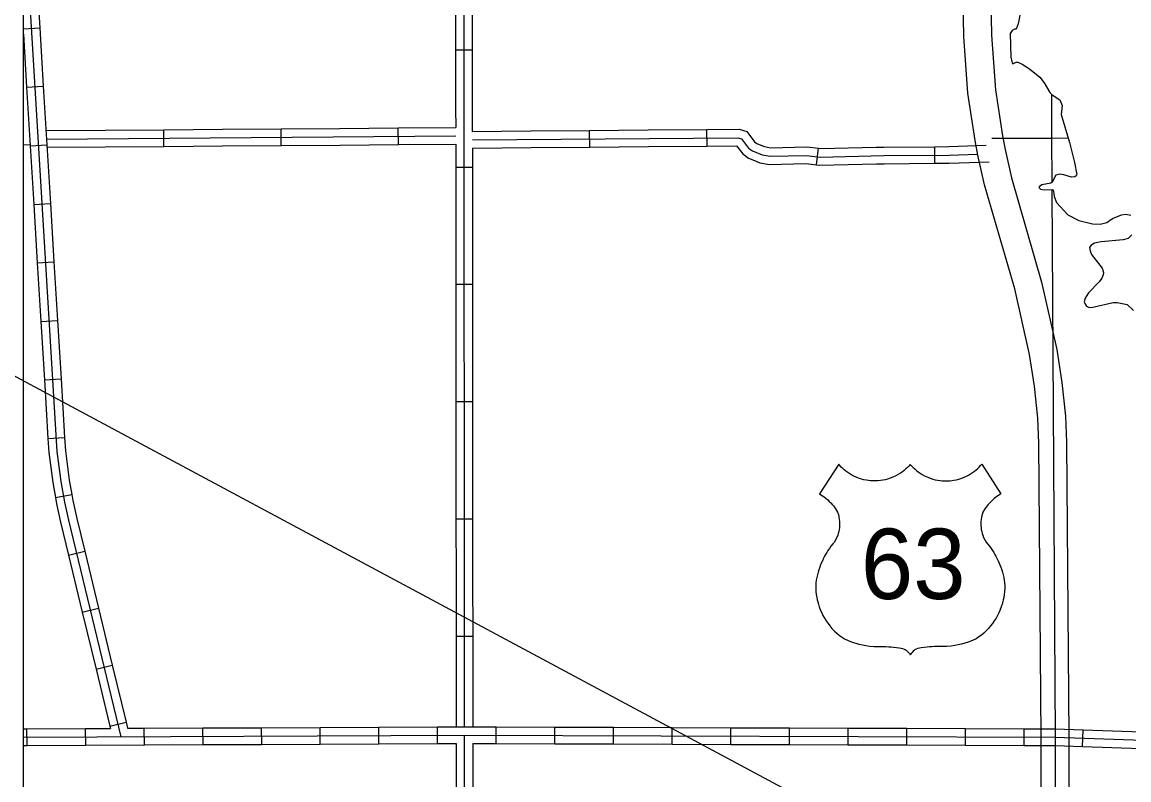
# Model space of a CAD drawing. Extents: x 982240 to 1103002, y 974866 to 1054902.
# Drawn here: x 1018606 to 1028568, y 996650 to 1003474 of the extents above; entities that cross this region are included whole.
import ezdxf

# ---------------------------------------------------------------- set-up
doc = ezdxf.new("R2010")
doc.units = 0
for name, color, linetype in [('15', 7, 'Continuous'), ('22', 7, 'Continuous'), ('32', 7, 'Continuous'), ('45', 7, 'Continuous'), ('5', 7, 'Continuous'), ('9', 7, 'Continuous'), ('R_Draft', 7, 'Continuous')]:
    doc.layers.add(name, color=color, linetype=linetype)

msp = doc.modelspace()

# ---------------------------------------------------------------- linework, layer by layer
at = {"layer": '15'}
for points in [[(1027756.9, 999682.4), (1027748.8, 999907.5), (1027717.7, 1000195.3), (1027673, 1000479.3), (1027540.7, 1001071.6), (1027269.7, 1002010.1), (1027208.3, 1002274.5), (1027183.4, 1002408.2), (1027119.6, 1002835), (1027081.4, 1003344.1), (1027076.2, 1003680.1), (1027091.5, 1003973.3), (1027115.3, 1004225.1), (1027144.1, 1004456.7)], [(1027390.8, 1004416.4), (1027363.8, 1004197.9), (1027340.9, 1003955), (1027326.3, 1003675.5), (1027331.2, 1003355.4), (1027368.2, 1002862.9), (1027430, 1002449.6), (1027453.1, 1002325.7), (1027511.7, 1002073.1), (1027783, 1001133.6), (1027918.7, 1000526.1), (1027965.6, 1000228.2), (1027998.3, 999925.5), (1028006.7, 999691.4)], [(1027778.7, 994300), (1027779, 997032.7), (1027756.8, 999685.8)], [(1028006.8, 999687.9), (1028029, 997033.8), (1028028.7, 994298.4)]]:
    msp.add_lwpolyline(points, dxfattribs=at)
at = {"layer": '22'}
for points in [[(1026600, 999491.1), (1026586.8, 999476.3), (1026574.3, 999463.4), (1026560, 999450), (1026544.5, 999436.8), (1026529.6, 999425.2), (1026511.6, 999412.6), (1026492.2, 999400.5), (1026470.1, 999388.4), (1026442.1, 999375.4), (1026420.6, 999367), (1026396.3, 999359.2), (1026374.1, 999353.4), (1026353.6, 999349.1), (1026332, 999345.8), (1026312.1, 999343.8), (1026284.9, 999342.5), (1026262.8, 999342.8), (1026243.6, 999343.9), (1026225.2, 999345.9), (1026206.7, 999348.7), (1026183.3, 999353.4), (1026161.7, 999359.1), (1026135.4, 999367.6), (1026113.1, 999376.4), (1026092.9, 999385.7), (1026074.3, 999395.4), (1026057.2, 999405.5), (1026038.1, 999418.1), (1026020.5, 999431), (1026005.4, 999443.3), (1025992.6, 999454.6), (1025979.6, 999467.2), (1025966.9, 999480.7), (1025956.5, 999492.5), (1025783.4, 999224.8), (1025795.8, 999217.5), (1025810.5, 999207.8), (1025824.5, 999197.9), (1025843.1, 999183.4), (1025857.9, 999170.6), (1025871.1, 999158.3), (1025884.5, 999144.7), (1025898.2, 999129.5), (1025908.1, 999117.6), (1025917.8, 999105), (1025927.6, 999091.3), (1025937.2, 999076.8), (1025946.1, 999059.8), (1025952.8, 999039), (1025957.9, 999018.2), (1025961.7, 998996.2), (1025963.8, 998975.7), (1025964.5, 998955.8), (1025964, 998937.3), (1025962.8, 998922.4), (1025960.3, 998904.2), (1025956.9, 998887), (1025952.1, 998868.5), (1025946.9, 998852.2), (1025939.8, 998833.9), (1025928.5, 998810.3), (1025917, 998791.8), (1025903.1, 998775.1), (1025886.1, 998753.3), (1025872.4, 998734.2), (1025859.5, 998715.2), (1025847.8, 998696.5), (1025837.9, 998679.7), (1025829.2, 998664), (1025819.4, 998645.3), (1025809, 998623.5), (1025799.6, 998602.1), (1025793.1, 998586.2), (1025785.4, 998565.9), (1025777, 998540.9), (1025770.3, 998520.2), (1025764, 998497.5), (1025758.2, 998471.2), (1025754.3, 998447.9), (1025751.6, 998423.5), (1025750, 998396.9), (1025749.8, 998371.9), (1025751, 998347.4), (1025754, 998318.7), (1025758.4, 998291.5), (1025762.9, 998270.9), (1025767.6, 998252.8), (1025773.5, 998232.4), (1025781.5, 998207), (1025792.9, 998176.1), (1025802.8, 998153.4), (1025814.2, 998130.1), (1025826.7, 998107.2), (1025843, 998080.9), (1025859.9, 998056.8), (1025876.2, 998035.7), (1025894.7, 998014.2), (1025918.6, 997989.4), (1025938.9, 997970.6), (1025959.8, 997953.1)], [(1026600, 999491.1), (1026613.1, 999476.3), (1026625.7, 999463.4), (1026640, 999450), (1026655.4, 999436.8), (1026670.3, 999425.2), (1026688.4, 999412.6), (1026707.8, 999400.5), (1026729.8, 999388.4), (1026757.8, 999375.4), (1026779.3, 999367), (1026803.6, 999359.2), (1026825.8, 999353.4), (1026846.3, 999349.1), (1026867.9, 999345.8), (1026887.8, 999343.8), (1026915, 999342.5), (1026937.1, 999342.8), (1026956.4, 999343.9), (1026974.7, 999345.9), (1026993.3, 999348.7), (1027016.6, 999353.4), (1027038.2, 999359.1), (1027064.5, 999367.6), (1027086.8, 999376.4), (1027107, 999385.7), (1027125.6, 999395.4), (1027142.7, 999405.5), (1027161.9, 999418.1), (1027179.4, 999431), (1027194.5, 999443.3), (1027207.3, 999454.6), (1027220.3, 999467.2), (1027233.1, 999480.7), (1027243.4, 999492.5), (1027416.5, 999224.8), (1027404.2, 999217.5), (1027389.4, 999207.8), (1027375.5, 999197.9), (1027356.9, 999183.4), (1027342, 999170.6), (1027328.9, 999158.3), (1027315.5, 999144.7), (1027301.7, 999129.5), (1027291.9, 999117.6), (1027282.2, 999105), (1027272.3, 999091.3), (1027262.7, 999076.8), (1027253.9, 999059.8), (1027247.2, 999039), (1027242, 999018.2), (1027238.2, 998996.2), (1027236.2, 998975.7), (1027235.5, 998955.8), (1027236, 998937.3), (1027237.2, 998922.4), (1027239.6, 998904.2), (1027243, 998887), (1027247.8, 998868.5), (1027253, 998852.2), (1027260.2, 998833.9), (1027271.4, 998810.3), (1027283, 998791.8), (1027296.9, 998775.1), (1027313.8, 998753.3), (1027327.6, 998734.2), (1027340.4, 998715.2), (1027352.2, 998696.5), (1027362.1, 998679.7), (1027370.8, 998664), (1027380.5, 998645.3), (1027391, 998623.5), (1027400.4, 998602.1), (1027406.9, 998586.2), (1027414.5, 998565.9), (1027423, 998540.9), (1027429.6, 998520.2), (1027435.9, 998497.5), (1027441.7, 998471.2), (1027445.6, 998447.9), (1027448.4, 998423.5), (1027450, 998396.9), (1027450.1, 998371.9), (1027449, 998347.4), (1027446, 998318.7), (1027441.5, 998291.5), (1027437.1, 998270.9), (1027432.3, 998252.8), (1027426.4, 998232.4), (1027418.5, 998207), (1027407, 998176.1), (1027397.2, 998153.4), (1027385.8, 998130.1), (1027373.2, 998107.2), (1027356.9, 998080.9), (1027340.1, 998056.8), (1027323.8, 998035.7), (1027305.3, 998014.2), (1027281.3, 997989.4), (1027261, 997970.6), (1027240.1, 997953.1)], [(1025959.8, 997953.1), (1025981.5, 997936.6), (1026007.6, 997919.6), (1026040.4, 997904.9), (1026078.7, 997890.2), (1026110, 997880.1), (1026138.1, 997872.3), (1026169.9, 997864.9), (1026199.8, 997859.4), (1026231.9, 997855), (1026272.4, 997851.5), (1026303.4, 997850.4), (1026329.9, 997850.6), (1026355.6, 997850.3), (1026381.4, 997849.5), (1026405.9, 997848.3), (1026427.2, 997846.8), (1026448.2, 997845.1), (1026475.1, 997842.3), (1026501.4, 997839), (1026517.1, 997836.8), (1026530.2, 997834.3), (1026545.9, 997827.7), (1026554.9, 997822.7), (1026562.8, 997817.5), (1026573.6, 997808.8), (1026583.9, 997798.4), (1026592.3, 997787.6), (1026600, 997775.1)], [(1027240.1, 997953.1), (1027218.4, 997936.6), (1027192.3, 997919.6), (1027159.6, 997904.9), (1027121.3, 997890.2), (1027090, 997880.1), (1027061.8, 997872.3), (1027030, 997864.9), (1027000.1, 997859.4), (1026968, 997855), (1026927.5, 997851.5), (1026896.6, 997850.4), (1026870.1, 997850.6), (1026844.3, 997850.3), (1026818.5, 997849.5), (1026794.1, 997848.3), (1026772.8, 997846.8), (1026751.8, 997845.1), (1026724.9, 997842.3), (1026698.6, 997839), (1026682.8, 997836.8), (1026669.8, 997834.3), (1026654, 997827.7), (1026645, 997822.7), (1026637.1, 997817.5), (1026626.3, 997808.8), (1026616, 997798.4), (1026607.6, 997787.6), (1026600, 997775.1)]]:
    msp.add_lwpolyline(points, dxfattribs=at)
at = {"layer": '32'}
for p, q in [((1018616.9, 1003414.1), (1018763.6, 1003423)), ((1018646, 1002886.9), (1018795.7, 1002896)), ((1018678, 1002359.9), (1018827.7, 1002369)), ((1018710.1, 1001832.8), (1018859.8, 1001841.9)), ((1018742.1, 1001305.8), (1018891.9, 1001314.9)), ((1018774.2, 1000778.8), (1018923.9, 1000787.9)), ((1018806.3, 1000251.8), (1018956, 1000260.9)), ((1018838.3, 999724.7), (1018988, 999733.9)), ((1018904.7, 999193.2), (1019052.6, 999218.7)), ((1019023, 998673.7), (1019168.8, 998708.9)), ((1019147.1, 998160.5), (1019292.9, 998195.7)), ((1019271.2, 997647.3), (1019417, 997682.5)), ((1019395.3, 997134.1), (1019541.1, 997169.3)), ((1019395.3, 997134.1), (1019400.3, 997113.6)), ((1019541.1, 997169.3), (1019554.4, 997114.3)), ((1018649.8, 996960.3), (1018649.2, 997110.3)), ((1019177.2, 997112.6), (1019400.3, 997113.6)), ((1019177.8, 996962.6), (1019177.2, 997112.6)), ((1019554.4, 997114.3), (1019705.2, 997115)), ((1019705.8, 996965), (1019705.2, 997115)), ((1020233.8, 996967.3), (1020233.2, 997117.3)), ((1020761.8, 996969.6), (1020761.2, 997119.6)), ((1021289.8, 996972), (1021289.2, 997122)), ((1021817.8, 996974.3), (1021817.1, 997124.3)), ((1022345.8, 996976.6), (1022345.1, 997126.6)), ((1022873.2, 996976.7), (1022873.7, 997126.7)), ((1023401.2, 996974.9), (1023401.7, 997124.9)), ((1023929.2, 996973.1), (1023929.7, 997123.1)), ((1024457.2, 996971.3), (1024457.7, 997121.3)), ((1024985.2, 996969.5), (1024985.7, 997119.5)), ((1025513.2, 996967.8), (1025513.7, 997117.8)), ((1026041.2, 996966), (1026041.7, 997116)), ((1026569.2, 996964.2), (1026569.7, 997114.2)), ((1027097.2, 996962.4), (1027097.7, 997112.4)), ((1027625.2, 996960.6), (1027625.7, 997110.6)), ((1028150.8, 996951.1), (1028155.9, 997101.1)), ((1022345.8, 996976.6), (1022512.2, 996977.4)), ((1022512.2, 996977.4), (1022512.3, 996523.3)), ((1022662.2, 996977.4), (1022873.2, 996976.7)), ((1022662.2, 996977.4), (1022662.3, 996523.3))]:
    msp.add_line(p, q, dxfattribs=at)
for points in [[(1018616.9, 1004576.7), (1018919.3, 999605.7), (1018954.6, 999337.6), (1018986.9, 999149.7), (1019022.7, 998987.9), (1019494.5, 997037.2)], [(1018731.6, 1003950), (1018763.6, 1003423)], [(1018763.6, 1003423), (1018795.7, 1002896)], [(1018616.9, 1003364.4), (1018646, 1002886.9)], [(1018646, 1002886.9), (1018678, 1002359.9)], [(1018795.7, 1002896), (1018827.7, 1002369)], [(1018678, 1002359.9), (1018710.1, 1001832.8)], [(1018827.7, 1002369), (1018859.8, 1001841.9)], [(1018710.1, 1001832.8), (1018742.1, 1001305.8)], [(1018859.8, 1001841.9), (1018891.9, 1001314.9)], [(1018891.9, 1001314.9), (1018923.9, 1000787.9)], [(1018742.1, 1001305.8), (1018774.2, 1000778.8)], [(1018774.2, 1000778.8), (1018806.3, 1000251.8)], [(1018923.9, 1000787.9), (1018956, 1000260.9)], [(1018806.3, 1000251.8), (1018838.3, 999724.7)], [(1018956, 1000260.9), (1018988, 999733.9)], [(1018838.3, 999724.7), (1018846, 999598.6), (1018881.8, 999326.5), (1018904.7, 999193.2)], [(1018988, 999733.9), (1018995.4, 999613), (1019030.1, 999349), (1019052.6, 999218.7)], [(1018904.7, 999193.2), (1018914.7, 999135.5), (1018951, 998971.3), (1019023, 998673.7)], [(1019052.6, 999218.7), (1019061.9, 999164.4), (1019097.1, 999005.2), (1019168.8, 998708.9)], [(1019023, 998673.7), (1019147.1, 998160.5)], [(1019168.8, 998708.9), (1019292.9, 998195.7)], [(1019147.1, 998160.5), (1019271.2, 997647.3)], [(1019292.9, 998195.7), (1019417, 997682.5)], [(1019271.2, 997647.3), (1019395.3, 997134.1)], [(1019417, 997682.5), (1019541.1, 997169.3)], [(1018616.9, 997110.2), (1018649.2, 997110.3)], [(1018616.9, 997033.8), (1022585.8, 997051.3), (1027904, 997033.2)], [(1018649.2, 997110.3), (1019177.2, 997112.6)], [(1019705.2, 997115), (1020233.2, 997117.3)], [(1020233.2, 997117.3), (1020761.2, 997119.6)], [(1020761.2, 997119.6), (1021289.2, 997122)], [(1021289.2, 997122), (1021817.1, 997124.3)], [(1021817.1, 997124.3), (1022345.1, 997126.6)], [(1022345.1, 997126.6), (1022585.8, 997127.7), (1022873.7, 997126.7)], [(1022585.8, 997051.3), (1022587.5, 991642.2), (1022477.3, 987555.6)], [(1022873.7, 997126.7), (1023401.7, 997124.9)], [(1023401.7, 997124.9), (1023929.7, 997123.1)], [(1023929.7, 997123.1), (1024457.7, 997121.3)], [(1024457.7, 997121.3), (1024985.7, 997119.5)], [(1024985.7, 997119.5), (1025513.7, 997117.8)], [(1025513.7, 997117.8), (1026041.7, 997116)], [(1026041.7, 997116), (1026569.7, 997114.2)], [(1026569.7, 997114.2), (1027097.7, 997112.4)], [(1027097.7, 997112.4), (1027625.7, 997110.6)], [(1027625.7, 997110.6), (1027905.4, 997109.6), (1028155.9, 997101.1)], [(1027904, 997033.2), (1033266.6, 996849.8)], [(1028155.9, 997101.1), (1028683.6, 997083)], [(1018616.9, 996960.2), (1018649.8, 996960.3)], [(1018649.8, 996960.3), (1019177.8, 996962.6)], [(1019177.8, 996962.6), (1019705.8, 996965)], [(1019705.8, 996965), (1020233.8, 996967.3)], [(1020233.8, 996967.3), (1020761.8, 996969.6)], [(1020761.8, 996969.6), (1021289.8, 996972)], [(1021289.8, 996972), (1021817.8, 996974.3)], [(1021817.8, 996974.3), (1022345.8, 996976.6)], [(1022873.2, 996976.7), (1023401.2, 996974.9)], [(1023401.2, 996974.9), (1023929.2, 996973.1)], [(1023929.2, 996973.1), (1024457.2, 996971.3)], [(1024457.2, 996971.3), (1024985.2, 996969.5)], [(1024985.2, 996969.5), (1025513.2, 996967.8)], [(1025513.2, 996967.8), (1026041.2, 996966)], [(1026041.2, 996966), (1026569.2, 996964.2)], [(1026569.2, 996964.2), (1027097.2, 996962.4)], [(1027097.2, 996962.4), (1027625.2, 996960.6)], [(1027625.2, 996960.6), (1027902.6, 996959.6), (1028150.8, 996951.1)], [(1028150.8, 996951.1), (1028678.5, 996933.1)]]:
    msp.add_lwpolyline(points, dxfattribs=at)
at = {"layer": '45'}
for p, q in [((1022580.4, 1004281.2), (1022585.7, 997127.7)), ((1022507.6, 1003225.1), (1022657.6, 1003225.2)), ((1022508, 1002697.1), (1022508.1, 1002525.1)), ((1022658, 1002697.2), (1022658.1, 1002489.8)), ((1020937.1, 1002363.1), (1020936, 1002513.1)), ((1021991.9, 1002521.1), (1022508.1, 1002525.1)), ((1021993.1, 1002371.1), (1021991.9, 1002521.1)), ((1018820, 1002496.9), (1019352, 1002501)), ((1018824.6, 1002420.5), (1022508.2, 1002448.7)), ((1019881.1, 1002355), (1019880, 1002505)), ((1022658.1, 1002489.8), (1023185.5, 1002494.2)), ((1023714.8, 1002348.6), (1023713.5, 1002498.6)), ((1024770.7, 1002357.4), (1024769.5, 1002507.4)), ((1018829.1, 1002347), (1019353.2, 1002351)), ((1021993.1, 1002371.1), (1022508.2, 1002375.1)), ((1022508.2, 1002375.1), (1022508.4, 1002169.1)), ((1022658.2, 1002339.8), (1023186.8, 1002344.2)), ((1022658.2, 1002339.8), (1022658.4, 1002169.2)), ((1025756.9, 1002188.7), (1025775.2, 1002337.6)), ((1026822.1, 1002202.5), (1026820.9, 1002352.5)), ((1022508.4, 1002169.1), (1022658.4, 1002169.2)), ((1022509.2, 1001113.1), (1022659.2, 1001113.2)), ((1022509.9, 1000057.1), (1022659.9, 1000057.2)), ((1022510.7, 999001.1), (1022660.7, 999001.2)), ((1022511.5, 997945.1), (1022661.5, 997945.2))]:
    msp.add_line(p, q, dxfattribs=at)
for points in [[(1022507.2, 1003753.1), (1022507.6, 1003225.1)], [(1022657.2, 1003753.2), (1022657.6, 1003225.2)], [(1022507.6, 1003225.1), (1022508, 1002697.1)], [(1022657.6, 1003225.2), (1022658, 1002697.2)], [(1020408, 1002509), (1020936, 1002513.1)], [(1020936, 1002513.1), (1021463.9, 1002517.1)], [(1021463.9, 1002517.1), (1021991.9, 1002521.1)], [(1024769.5, 1002507.4), (1025059.6, 1002509.8), (1025128, 1002488.7), (1025197.8, 1002395.5), (1025217.6, 1002381.3), (1025270.6, 1002359.6)], [(1019352, 1002501), (1019880, 1002505)], [(1019880, 1002505), (1020408, 1002509)], [(1022658.2, 1002413.4), (1025048.4, 1002433.3), (1025081.7, 1002423.1), (1025143.8, 1002340.2), (1025180.4, 1002314), (1025266.4, 1002278.9), (1025337.8, 1002266.5), (1025665.2, 1002274.1), (1025788.8, 1002259), (1026363.5, 1002272.4), (1026949.5, 1002277.1), (1027205.6, 1002286.1)], [(1023185.5, 1002494.2), (1023713.5, 1002498.6)], [(1023713.5, 1002498.6), (1024241.5, 1002503)], [(1024241.5, 1002503), (1024769.5, 1002507.4)], [(1019353.2, 1002351), (1019881.1, 1002355)], [(1019881.1, 1002355), (1020409.1, 1002359)], [(1020409.1, 1002359), (1020937.1, 1002363.1)], [(1020937.1, 1002363.1), (1021465.1, 1002367.1)], [(1021465.1, 1002367.1), (1021993.1, 1002371.1)], [(1023186.8, 1002344.2), (1023714.8, 1002348.6)], [(1023714.8, 1002348.6), (1024242.7, 1002353)], [(1024242.7, 1002353), (1024770.7, 1002357.4)], [(1024770.7, 1002357.4), (1025037.3, 1002359.6), (1025091.7, 1002287), (1025144.6, 1002249.1), (1025213.9, 1002220.8)], [(1025270.6, 1002359.6), (1025287.6, 1002352.7), (1025343.5, 1002343), (1025669, 1002350.6), (1025775.2, 1002337.6)], [(1025775.2, 1002337.6), (1025792.6, 1002335.5), (1026291.8, 1002347.1)], [(1026291.8, 1002347.1), (1026362.3, 1002348.8), (1026820.9, 1002352.5)], [(1026820.9, 1002352.5), (1026947.9, 1002353.5), (1027282.7, 1002365.3)], [(1025213.9, 1002220.8), (1025246, 1002207.7), (1025332.3, 1002192.7), (1025661.6, 1002200.4), (1025756.9, 1002188.7)], [(1026822.1, 1002202.5), (1026951.1, 1002203.5), (1027309.9, 1002216.1)], [(1022508.4, 1002169.1), (1022508.8, 1001641.1)], [(1022658.4, 1002169.2), (1022658.8, 1001641.2)], [(1025756.9, 1002188.7), (1025785.2, 1002185.2), (1026295.3, 1002197.2)], [(1026295.3, 1002197.2), (1026364.7, 1002198.8), (1026822.1, 1002202.5)], [(1022508.8, 1001641.1), (1022509.2, 1001113.1)], [(1022658.8, 1001641.2), (1022659.2, 1001113.2)], [(1022509.2, 1001113.1), (1022509.6, 1000585.1)], [(1022659.2, 1001113.2), (1022659.6, 1000585.2)], [(1022509.6, 1000585.1), (1022509.9, 1000057.1)], [(1022659.6, 1000585.2), (1022659.9, 1000057.2)], [(1022509.9, 1000057.1), (1022510.3, 999529.1)], [(1022659.9, 1000057.2), (1022660.3, 999529.2)], [(1022510.3, 999529.1), (1022510.7, 999001.1)], [(1022660.3, 999529.2), (1022660.7, 999001.2)], [(1022510.7, 999001.1), (1022511.1, 998473.1)], [(1022660.7, 999001.2), (1022661.1, 998473.2)], [(1022511.1, 998473.1), (1022511.5, 997945.1)], [(1022661.1, 998473.2), (1022661.5, 997945.2)], [(1022511.5, 997945.1), (1022511.9, 997417.1)], [(1022661.5, 997945.2), (1022661.9, 997417.2)], [(1022511.9, 997417.1), (1022512.1, 997127.7)], [(1022661.9, 997417.2), (1022662.1, 997127.8)]]:
    msp.add_lwpolyline(points, dxfattribs=at)
at = {"layer": '5'}
for points in [[(1027871.3, 1002820.4), (1027872.7, 1002430.1)], [(1027333.5, 1002428.4), (1027872.7, 1002430.1), (1028017.8, 1002430.6)], [(1027872.7, 1002430.1), (1027875, 1002033.6)], [(1018616.9, 1002370.1), (1018677.9, 1002370.7)], [(1027875.4, 1001961.9), (1027904, 997033.2)], [(1027904, 997033.2), (1027903.7, 994578.9)]]:
    msp.add_lwpolyline(points, dxfattribs=at)
at = {"layer": '9'}
for points in [[(1027599.9, 1003597.5), (1027571.1, 1003457.3), (1027553.1, 1003411.7), (1027537.2, 1003409.4), (1027517.3, 1003399.9), (1027499.9, 1003372.4), (1027505.9, 1003158.8), (1027516.1, 1003106.8), (1027524.3, 1003099), (1027552, 1003114.7), (1027567, 1003113), (1027606.5, 1003096.9), (1027674.6, 1003054.3), (1027767.5, 1002979.2), (1027805.7, 1002928), (1027856.8, 1002839.8), (1027876.4, 1002819.2), (1027946.5, 1002773.7), (1027967.7, 1002724), (1027959.6, 1002642.6), (1028032.5, 1002390.4), (1028078.7, 1002209.8), (1028098.2, 1002102.9), (1028093.5, 1002089.8), (1028080.7, 1002081.4), (1028050.8, 1002076.7), (1027981.1, 1002099.2), (1027946.9, 1002104.4), (1027910.1, 1002094.5), (1027877.5, 1002032.5), (1027866.6, 1002024.3), (1027783.8, 1002009.3), (1027761.2, 1001991.7), (1027759.4, 1001982.6), (1027773.7, 1001968.9), (1027804.9, 1001964.6), (1027883, 1001965.4), (1027890.3, 1001951.6), (1027896.4, 1001904.5)], [(1027896.4, 1001904.5), (1027917.7, 1001849.8), (1028019.5, 1001739.8), (1028116.8, 1001687.9), (1028241.8, 1001656.7), (1028310.9, 1001655.3), (1028369.7, 1001669.8), (1028420, 1001704.1), (1028501.3, 1001740.1), (1028539.3, 1001745), (1028584.6, 1001735)], [(1028595.7, 1001557.6), (1028562.4, 1001524.8), (1028517.5, 1001514.7), (1028319.6, 1001496), (1028259.8, 1001483.6), (1028224.2, 1001462.7), (1028213.6, 1001445.3), (1028218.3, 1001415.4), (1028232.1, 1001381.6), (1028329.1, 1001257.4), (1028340, 1001219.5), (1028337.5, 1001199.4), (1028323.2, 1001167.9), (1028299.9, 1001134.3), (1028205, 1001035.7), (1028174.1, 1000986.8), (1028165.7, 1000956.5), (1028173.3, 1000932.6), (1028186.7, 1000916.9), (1028211, 1000904.4), (1028243, 1000907.2), (1028427.4, 1000947.6), (1028462.4, 1000950.4), (1028553, 1000931.5), (1028610.4, 1000876.6)]]:
    msp.add_lwpolyline(points, dxfattribs=at)
at = {"layer": 'R_Draft'}
msp.add_line((1016927.5, 1001150.1), (1027888.7, 995272.9), dxfattribs=at)
msp.add_lwpolyline([(1018616.9, 1018048.7), (1063839.6, 1018048.7), (1063839.6, 987555.6), (1018616.9, 987555.6)], close=True, dxfattribs=at)
msp.add_lwpolyline([(1018616.9, 1018048.7), (1063839.6, 1018048.7), (1063839.6, 987555.6), (1018616.9, 987555.6)], close=True, dxfattribs=at)

# ---------------------------------------------------------------- texts
at = {"layer": '22'}
msp.add_text('63', height=633.6, dxfattribs=at).set_placement((1026155.2, 998278.8))

doc.saveas('drawing.dxf')
